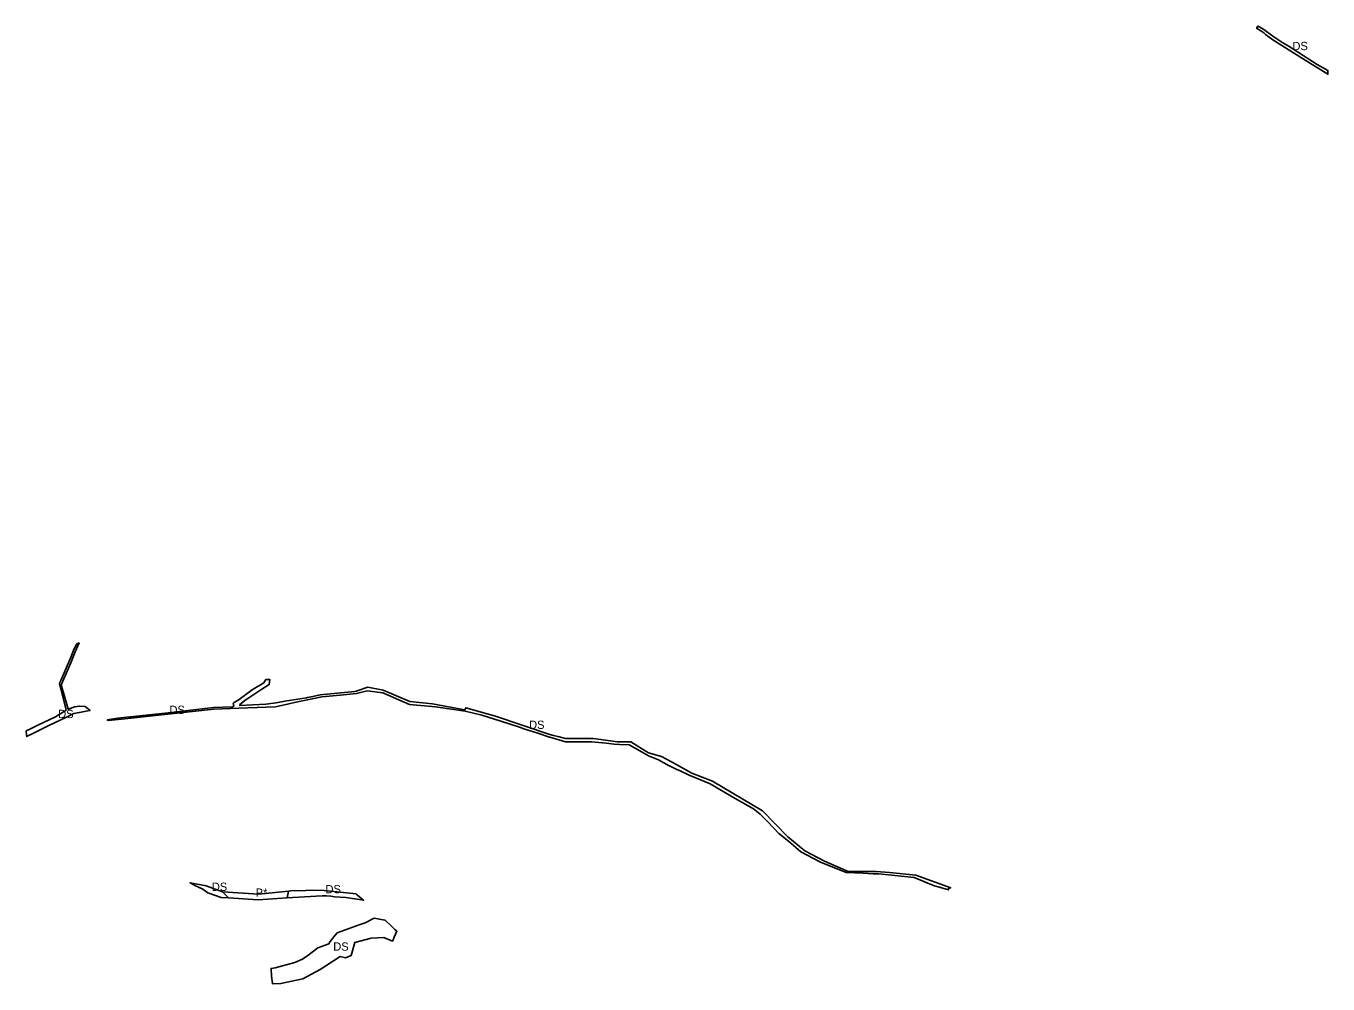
# Model space of a CAD drawing. Extents: x -477403 to -475386, y -1156331 to -1149624.
# Drawn here: x -477403 to -475832, y -1150779 to -1149624 of the extents above; entities that cross this region are included whole.
import ezdxf

# ---------------------------------------------------------------- set-up
doc = ezdxf.new("R2010")
doc.units = 0
doc.layers.add('4', color=7, linetype='Continuous')
doc.layers.add('43', color=7, linetype='Continuous')

msp = doc.modelspace()

# ---------------------------------------------------------------- linework, layer by layer
at = {"layer": '4'}
for points in [[(-475909.47, -1149628.2), (-475898.44, -1149636.26), (-475886.65, -1149644.07), (-475880.05, -1149647.85), (-475845.23, -1149670.38), (-475837.67, -1149674.41), (-475832.07, -1149677.43), (-475832.11, -1149682.1), (-475862.83, -1149663.1), (-475898.58, -1149640.68), (-475907.55, -1149634.16), (-475909.41, -1149632.18), (-475913.02, -1149629.62), (-475918.255, -1149626.772), (-475917.915, -1149626.14), (-475916.524, -1149624.033), (-475914.26, -1149625.38)], [(-477357.44, -1150427.741), (-477351.602, -1150447.758), (-477343.545, -1150444.88), (-477343.518, -1150444.87), (-477338.271, -1150443.875), (-477331.07, -1150444.414), (-477325.23, -1150449.02), (-477325.81, -1150449.12), (-477338.17, -1150451.509), (-477341.02, -1150452.06), (-477342.3, -1150452.3), (-477345.07, -1150452.84), (-477353.73, -1150457.06), (-477375.08, -1150467.47), (-477396.72, -1150478.02), (-477400.44, -1150479.83), (-477401.48, -1150480.787), (-477401.843, -1150479.196), (-477402.562, -1150473.884), (-477400.747, -1150472.912), (-477399.701, -1150472.352), (-477388.435, -1150466.94), (-477367.083, -1150456.685), (-477354.305, -1150448.723), (-477360.306, -1150424.206), (-477362.05, -1150417.08), (-477361.75, -1150415.47), (-477360.39, -1150413.15), (-477348.8, -1150386.14), (-477345.27, -1150376.87), (-477341.872, -1150369.057), (-477338.612, -1150367.833), (-477343.21, -1150378.33), (-477348.6, -1150391.63), (-477359.68, -1150417.28), (-477359.73, -1150419.89)], [(-477144.78, -1150441.88), (-477144.75, -1150443.13), (-477113.3, -1150441.62), (-477100.91, -1150440.11), (-477090.53, -1150438.09), (-477064.44, -1150433.81), (-477062.91, -1150433.56), (-477056.77, -1150432.45), (-477047.9, -1150430.23), (-477006.07, -1150426.3), (-477004.37, -1150425.73), (-476990.45, -1150421.06), (-476971.91, -1150424.69), (-476939.76, -1150438.19), (-476912.45, -1150441.11), (-476875.77, -1150448.17), (-476873.05, -1150448.47), (-476872.24, -1150445.95), (-476846.24, -1150453.21), (-476836.26, -1150456.23), (-476803.01, -1150467.12), (-476770.55, -1150478.1), (-476766.47, -1150479.19), (-476761.06, -1150480.64), (-476751.71, -1150483.14), (-476738.06, -1150483.06), (-476717.85, -1150482.94), (-476691.94, -1150486.64), (-476688.92, -1150487.07), (-476673.2, -1150487.07), (-476656.78, -1150496.92), (-476651.53, -1150500.07), (-476635.91, -1150504.61), (-476624.08, -1150511.14), (-476599.43, -1150524.76), (-476574.34, -1150534.54), (-476514.37, -1150570.01), (-476483.64, -1150601.66), (-476463.18, -1150618.28), (-476439.29, -1150630.78), (-476410.67, -1150643.28), (-476376.91, -1150643.28), (-476361.09, -1150644.49), (-476329.04, -1150647.81), (-476287.07, -1150663.04), (-476287.335, -1150663.105), (-476287.6, -1150663.17), (-476289.92, -1150663.73), (-476290.01, -1150665.43), (-476307.89, -1150660.05), (-476331.18, -1150650.38), (-476373.73, -1150646.32), (-476380.57, -1150645.95), (-476392.92, -1150645.5), (-476413.18, -1150644.36), (-476444.17, -1150632.27), (-476467.77, -1150619.68), (-476482.88, -1150606.75), (-476494.33, -1150597.6), (-476507.8, -1150583.47), (-476517.02, -1150574.3), (-476525.18, -1150567.69), (-476547.16, -1150555.24), (-476577.27, -1150537.56), (-476602.52, -1150527.19), (-476614.41, -1150521.73), (-476617.65, -1150520.18), (-476626.2, -1150516.12), (-476626.77, -1150515.85), (-476639.7, -1150508.81), (-476651.65, -1150503.79), (-476662.19, -1150497.77), (-476675.05, -1150490.42), (-476686.61, -1150490.19), (-476693.17, -1150489.75), (-476702.72, -1150488.66), (-476720.47, -1150487.09), (-476751.72, -1150486.94), (-476770.65, -1150481.52), (-476770.944, -1150481.424), (-476785.33, -1150476.71), (-476790.23, -1150475.1), (-476802.05, -1150471.22), (-476807.36, -1150469.48), (-476819.71, -1150465.35), (-476838.47, -1150459.08), (-476852.65, -1150454.99), (-476872.81, -1150450.13), (-476905.737, -1150445.082), (-476908.75, -1150444.62), (-476939.95, -1150441.86), (-476972.18, -1150427.88), (-476991, -1150425.31), (-477003.94, -1150428.92), (-477023.7, -1150430.54), (-477045.86, -1150432.87), (-477078.69, -1150439.57), (-477085.43, -1150441.06), (-477101.61, -1150444.62), (-477145.8, -1150446.52), (-477175.83, -1150447.71), (-477206.16, -1150450.84), (-477234.18, -1150453.8), (-477283.48, -1150459.36), (-477303.45, -1150461.34), (-477304.58, -1150460.49), (-477292.29, -1150458.65), (-477231.22, -1150452.2), (-477176.59, -1150445.45), (-477153.51, -1150444.84), (-477151.76, -1150443.65), (-477152.7, -1150440.57), (-477145.54, -1150435.79), (-477135.87, -1150428.63), (-477128.41, -1150423.44), (-477115.91, -1150415.98), (-477113.49, -1150411.9), (-477108.3, -1150412), (-477109.21, -1150417.9), (-477117.98, -1150423.49), (-477133.9, -1150434.12), (-477137.02, -1150435.84)], [(-477175.83, -1150447.71), (-477283.48, -1150459.36), (-477234.18, -1150453.8), (-477206.16, -1150450.84)], [(-477165.46, -1150667.83), (-477158.181, -1150675.223), (-477167.26, -1150674.64), (-477183.466, -1150669.054), (-477189.397, -1150664.743), (-477195.459, -1150661.733), (-477198.884, -1150660.04), (-477204.66, -1150656.945), (-477185.24, -1150660.42)], [(-477002.274, -1150672.171), (-476997.332, -1150676.24), (-476995.325, -1150677.891), (-476995.26, -1150677.945), (-476995.195, -1150677.999), (-477016.71, -1150674.86), (-477029.95, -1150673.68), (-477034.75, -1150673.26), (-477040.23, -1150672.77), (-477045.34, -1150672.85), (-477052.64, -1150673.21), (-477087.71, -1150674.93), (-477085.765, -1150666.867), (-477083.25, -1150666.61), (-477046.85, -1150665.89), (-477004.44, -1150670.389), (-477004.36, -1150670.455), (-477004.28, -1150670.52)], [(-476958.36, -1150722.67), (-476959.683, -1150725.657), (-476960.278, -1150727.001), (-476960.339, -1150727.14), (-476960.401, -1150727.28), (-476970.89, -1150723.02), (-476986.21, -1150723.66), (-477005.99, -1150728.91), (-477010.45, -1150744.67), (-477017.29, -1150747.26), (-477023.47, -1150745.96), (-477047.93, -1150761.43), (-477068.57, -1150772.57), (-477095.4, -1150778.26), (-477105.194, -1150778.892), (-477105.323, -1150778.326), (-477106.527, -1150769.434), (-477106.93, -1150760.47), (-477106.917, -1150760.179), (-477101.88, -1150759.56), (-477078.28, -1150752.94), (-477069.15, -1150749.2), (-477062.46, -1150744.59), (-477050.59, -1150735.53), (-477037.28, -1150730.5), (-477035.56, -1150727.58), (-477031.21, -1150722.03), (-477029.73, -1150720.14), (-477027.07, -1150717.41), (-477000.91, -1150707.68), (-476993.35, -1150705.05), (-476982.82, -1150699.69), (-476969.629, -1150701.809), (-476969.565, -1150701.87), (-476969.5, -1150701.93), (-476961.13, -1150709.77), (-476957.629, -1150713.049), (-476955.13, -1150715.39)]]:
    msp.add_lwpolyline(points, close=True, dxfattribs=at)
at = {"layer": '43'}
msp.add_lwpolyline([(-477087.71, -1150674.93), (-477122.38, -1150677.52), (-477158.181, -1150675.223), (-477165.46, -1150667.83), (-477121.87, -1150670.56), (-477085.765, -1150666.867)], close=True, dxfattribs=at)

# ---------------------------------------------------------------- texts
at = {"layer": '4'}
for p in [(-475874.942, -1149653.088), (-477363.81, -1150458.352), (-477229.569, -1150453.423), (-476795.74, -1150471.401), (-477178.468, -1150666.678), (-477041.367, -1150669.621), (-477031.97, -1150738.81)]:
    msp.add_text('DS', height=10, dxfattribs=at).set_placement(p)
at = {"layer": '43'}
msp.add_text('P*', height=10, dxfattribs=at).set_placement((-477125.545, -1150673.814))

doc.saveas('drawing.dxf')
